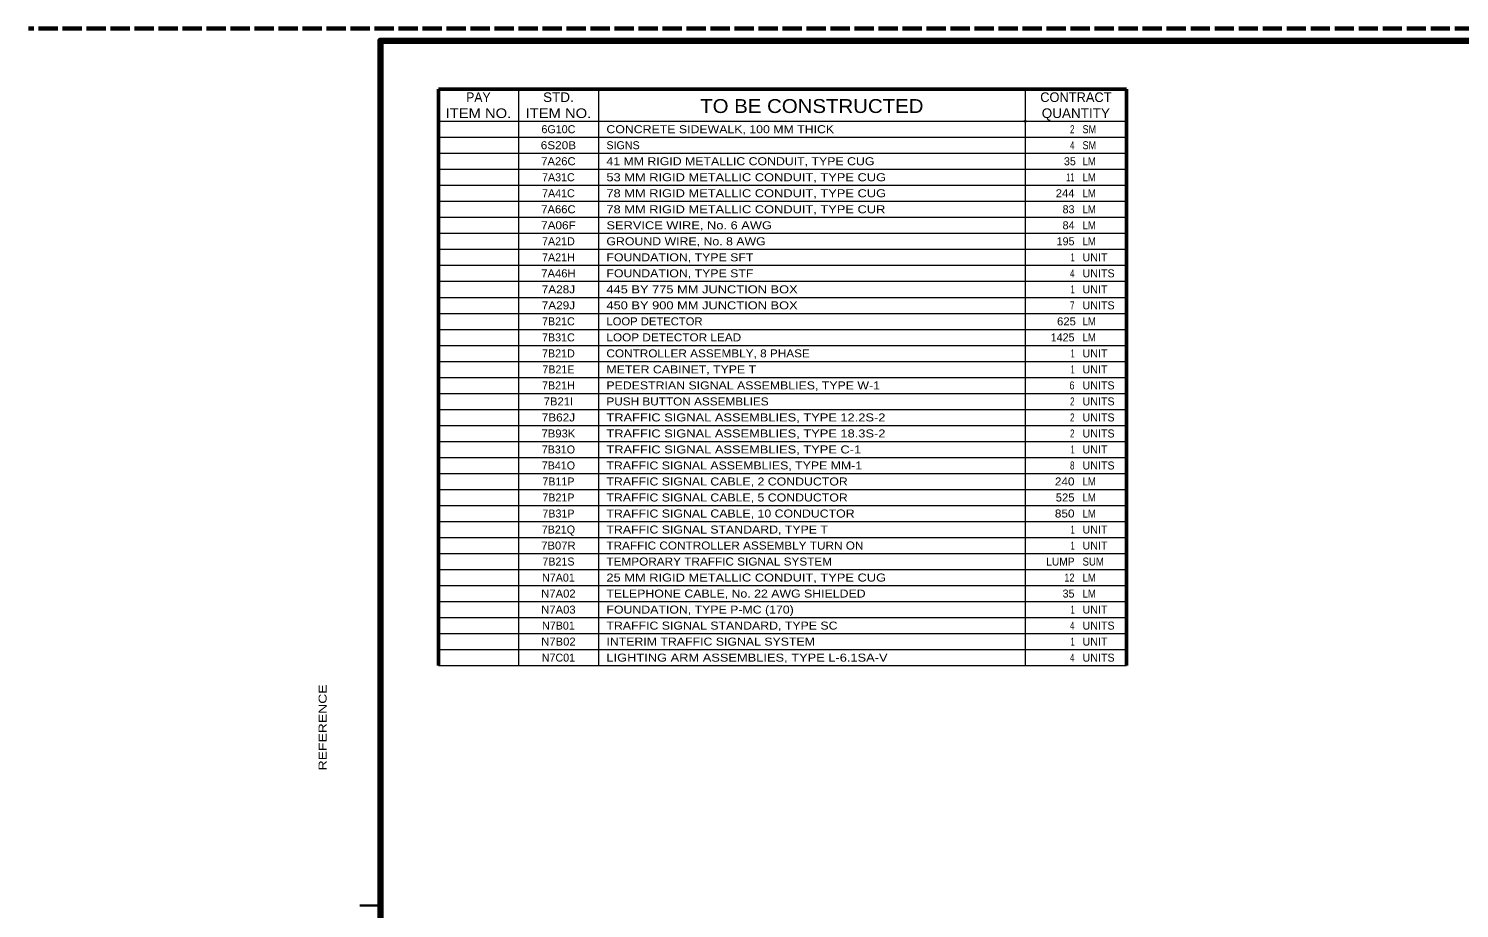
# Model space of a CAD drawing. Extents: x 168203 to 169864, y 223196 to 223870.
# Drawn here: x 169095.8 to 169229.9, y 223449.3 to 223531.7 of the extents above; entities that cross this region are included whole.
import ezdxf
from ezdxf.enums import TextEntityAlignment as Align

# ---------------------------------------------------------------- set-up
doc = ezdxf.new("R2010")
doc.units = 0
doc.header["$LTSCALE"] = 0.3
doc.header["$PDMODE"] = 32
doc.header["$PDSIZE"] = 0.15
doc.linetypes.add('LONG_DASHED', pattern=[7.5, 6, -1.5])
doc.layers.add('1', color=7, linetype='Continuous', lineweight=13)
doc.layers.add('10', color=7, linetype='Continuous', lineweight=13)

msp = doc.modelspace()

# ---------------------------------------------------------------- linework, layer by layer
at = {"layer": '1', "linetype": 'LONG_DASHED', "lineweight": 60}
msp.add_line((169364.0333, 223531.7489), (169095.8093, 223531.7489), dxfattribs=at)
at = {"layer": '1', "lineweight": 35}
msp.add_line((169126.8633, 223449.6089), (169128.7833, 223449.6089), dxfattribs=at)
at = {"layer": '1', "lineweight": 158}
msp.add_lwpolyline([(169361.2833, 223368.6089), (169361.2833, 223530.6089), (169128.7833, 223530.6089), (169128.7833, 223368.6089)], close=True, dxfattribs=at)
at = {"layer": '10', "lineweight": 53}
for p, q in [((169134.22, 223526.0771), (169198.72, 223526.0771)), ((169134.22, 223523.0771), (169134.22, 223526.0771)), ((169198.72, 223526.0771), (169198.72, 223523.0771)), ((169134.22, 223521.5771), (169134.22, 223523.0771)), ((169198.72, 223523.0771), (169198.72, 223521.5771)), ((169134.22, 223520.0771), (169134.22, 223521.5771)), ((169198.72, 223521.5771), (169198.72, 223520.0771)), ((169134.22, 223518.5771), (169134.22, 223520.0771)), ((169198.72, 223520.0771), (169198.72, 223518.5771)), ((169134.22, 223517.0771), (169134.22, 223518.5771)), ((169198.72, 223518.5771), (169198.72, 223517.0771)), ((169134.22, 223515.5771), (169134.22, 223517.0771)), ((169198.72, 223517.0771), (169198.72, 223515.5771)), ((169134.22, 223514.0771), (169134.22, 223515.5771)), ((169198.72, 223515.5771), (169198.72, 223514.0771)), ((169134.22, 223512.5771), (169134.22, 223514.0771)), ((169198.72, 223514.0771), (169198.72, 223512.5771)), ((169134.22, 223511.0771), (169134.22, 223512.5771)), ((169198.72, 223512.5771), (169198.72, 223511.0771)), ((169134.22, 223509.5771), (169134.22, 223511.0771)), ((169198.72, 223511.0771), (169198.72, 223509.5771)), ((169134.22, 223508.0771), (169134.22, 223509.5771)), ((169198.72, 223509.5771), (169198.72, 223508.0771)), ((169134.22, 223506.5771), (169134.22, 223508.0771)), ((169198.72, 223508.0771), (169198.72, 223506.5771)), ((169134.22, 223505.0771), (169134.22, 223506.5771)), ((169198.72, 223506.5771), (169198.72, 223505.0771)), ((169134.22, 223503.5771), (169134.22, 223505.0771)), ((169198.72, 223505.0771), (169198.72, 223503.5771)), ((169134.22, 223502.0771), (169134.22, 223503.5771)), ((169198.72, 223503.5771), (169198.72, 223502.0771)), ((169134.22, 223500.5771), (169134.22, 223502.0771)), ((169198.72, 223502.0771), (169198.72, 223500.5771)), ((169134.22, 223499.0771), (169134.22, 223500.5771)), ((169198.72, 223500.5771), (169198.72, 223499.0771)), ((169134.22, 223497.5771), (169134.22, 223499.0771)), ((169198.72, 223499.0771), (169198.72, 223497.5771)), ((169134.22, 223496.0771), (169134.22, 223497.5771)), ((169198.72, 223497.5771), (169198.72, 223496.0771)), ((169134.22, 223494.5771), (169134.22, 223496.0771)), ((169198.72, 223496.0771), (169198.72, 223494.5771)), ((169134.22, 223493.0771), (169134.22, 223494.5771)), ((169198.72, 223494.5771), (169198.72, 223493.0771)), ((169134.22, 223491.5771), (169134.22, 223493.0771)), ((169198.72, 223493.0771), (169198.72, 223491.5771)), ((169134.22, 223490.0771), (169134.22, 223491.5771)), ((169198.72, 223491.5771), (169198.72, 223490.0771)), ((169134.22, 223488.5771), (169134.22, 223490.0771)), ((169198.72, 223490.0771), (169198.72, 223488.5771)), ((169134.22, 223487.0771), (169134.22, 223488.5771)), ((169198.72, 223488.5771), (169198.72, 223487.0771)), ((169134.22, 223485.5771), (169134.22, 223487.0771)), ((169198.72, 223487.0771), (169198.72, 223485.5771)), ((169134.22, 223484.0771), (169134.22, 223485.5771)), ((169198.72, 223485.5771), (169198.72, 223484.0771)), ((169134.22, 223482.5771), (169134.22, 223484.0771)), ((169198.72, 223484.0771), (169198.72, 223482.5771)), ((169134.22, 223481.0771), (169134.22, 223482.5771)), ((169198.72, 223482.5771), (169198.72, 223481.0771)), ((169134.22, 223479.5771), (169134.22, 223481.0771)), ((169198.72, 223481.0771), (169198.72, 223479.5771)), ((169134.22, 223478.0771), (169134.22, 223479.5771)), ((169198.72, 223479.5771), (169198.72, 223478.0771)), ((169134.22, 223476.5771), (169134.22, 223478.0771)), ((169198.72, 223478.0771), (169198.72, 223476.5771)), ((169134.22, 223475.0771), (169134.22, 223476.5771)), ((169198.72, 223476.5771), (169198.72, 223475.0771)), ((169134.22, 223473.5771), (169134.22, 223475.0771)), ((169198.72, 223475.0771), (169198.72, 223473.5771)), ((169134.22, 223472.0771), (169134.22, 223473.5771)), ((169198.72, 223473.5771), (169198.72, 223472.0771))]:
    msp.add_line(p, q, dxfattribs=at)
at = {"layer": '10'}
for p, q in [((169141.72, 223526.0771), (169141.72, 223523.0771)), ((169149.22, 223526.0771), (169149.22, 223523.0771)), ((169189.22, 223526.0771), (169189.22, 223523.0771)), ((169134.22, 223523.0771), (169198.72, 223523.0771)), ((169141.72, 223523.0771), (169141.72, 223521.5771)), ((169149.22, 223523.0771), (169149.22, 223521.5771)), ((169189.22, 223523.0771), (169189.22, 223521.5771)), ((169134.22, 223521.5771), (169198.72, 223521.5771)), ((169141.72, 223521.5771), (169141.72, 223520.0771)), ((169149.22, 223521.5771), (169149.22, 223520.0771)), ((169189.22, 223521.5771), (169189.22, 223520.0771)), ((169134.22, 223520.0771), (169198.72, 223520.0771)), ((169141.72, 223520.0771), (169141.72, 223518.5771)), ((169149.22, 223520.0771), (169149.22, 223518.5771)), ((169189.22, 223520.0771), (169189.22, 223518.5771)), ((169134.22, 223518.5771), (169198.72, 223518.5771)), ((169141.72, 223518.5771), (169141.72, 223517.0771)), ((169149.22, 223518.5771), (169149.22, 223517.0771)), ((169189.22, 223518.5771), (169189.22, 223517.0771)), ((169134.22, 223517.0771), (169198.72, 223517.0771)), ((169141.72, 223517.0771), (169141.72, 223515.5771)), ((169149.22, 223517.0771), (169149.22, 223515.5771)), ((169189.22, 223517.0771), (169189.22, 223515.5771)), ((169134.22, 223515.5771), (169198.72, 223515.5771)), ((169141.72, 223515.5771), (169141.72, 223514.0771)), ((169149.22, 223515.5771), (169149.22, 223514.0771)), ((169189.22, 223515.5771), (169189.22, 223514.0771)), ((169134.22, 223514.0771), (169198.72, 223514.0771)), ((169141.72, 223514.0771), (169141.72, 223512.5771)), ((169149.22, 223514.0771), (169149.22, 223512.5771)), ((169189.22, 223514.0771), (169189.22, 223512.5771)), ((169134.22, 223512.5771), (169198.72, 223512.5771)), ((169141.72, 223512.5771), (169141.72, 223511.0771)), ((169149.22, 223512.5771), (169149.22, 223511.0771)), ((169189.22, 223512.5771), (169189.22, 223511.0771)), ((169134.22, 223511.0771), (169198.72, 223511.0771)), ((169141.72, 223511.0771), (169141.72, 223509.5771)), ((169149.22, 223511.0771), (169149.22, 223509.5771)), ((169189.22, 223511.0771), (169189.22, 223509.5771)), ((169134.22, 223509.5771), (169198.72, 223509.5771)), ((169141.72, 223509.5771), (169141.72, 223508.0771)), ((169149.22, 223509.5771), (169149.22, 223508.0771)), ((169189.22, 223509.5771), (169189.22, 223508.0771)), ((169134.22, 223508.0771), (169198.72, 223508.0771)), ((169141.72, 223508.0771), (169141.72, 223506.5771)), ((169149.22, 223508.0771), (169149.22, 223506.5771)), ((169189.22, 223508.0771), (169189.22, 223506.5771)), ((169134.22, 223506.5771), (169198.72, 223506.5771)), ((169141.72, 223506.5771), (169141.72, 223505.0771)), ((169149.22, 223506.5771), (169149.22, 223505.0771)), ((169189.22, 223506.5771), (169189.22, 223505.0771)), ((169134.22, 223505.0771), (169198.72, 223505.0771)), ((169141.72, 223505.0771), (169141.72, 223503.5771)), ((169149.22, 223505.0771), (169149.22, 223503.5771)), ((169189.22, 223505.0771), (169189.22, 223503.5771)), ((169134.22, 223503.5771), (169198.72, 223503.5771)), ((169141.72, 223503.5771), (169141.72, 223502.0771)), ((169149.22, 223503.5771), (169149.22, 223502.0771)), ((169189.22, 223503.5771), (169189.22, 223502.0771)), ((169134.22, 223502.0771), (169198.72, 223502.0771)), ((169141.72, 223502.0771), (169141.72, 223500.5771)), ((169149.22, 223502.0771), (169149.22, 223500.5771)), ((169189.22, 223502.0771), (169189.22, 223500.5771)), ((169134.22, 223500.5771), (169198.72, 223500.5771)), ((169141.72, 223500.5771), (169141.72, 223499.0771)), ((169149.22, 223500.5771), (169149.22, 223499.0771)), ((169189.22, 223500.5771), (169189.22, 223499.0771)), ((169134.22, 223499.0771), (169198.72, 223499.0771)), ((169141.72, 223499.0771), (169141.72, 223497.5771)), ((169149.22, 223499.0771), (169149.22, 223497.5771)), ((169189.22, 223499.0771), (169189.22, 223497.5771)), ((169134.22, 223497.5771), (169198.72, 223497.5771)), ((169141.72, 223497.5771), (169141.72, 223496.0771)), ((169149.22, 223497.5771), (169149.22, 223496.0771)), ((169189.22, 223497.5771), (169189.22, 223496.0771)), ((169134.22, 223496.0771), (169198.72, 223496.0771)), ((169141.72, 223496.0771), (169141.72, 223494.5771)), ((169149.22, 223496.0771), (169149.22, 223494.5771)), ((169189.22, 223496.0771), (169189.22, 223494.5771)), ((169134.22, 223494.5771), (169198.72, 223494.5771)), ((169141.72, 223494.5771), (169141.72, 223493.0771)), ((169149.22, 223494.5771), (169149.22, 223493.0771)), ((169189.22, 223494.5771), (169189.22, 223493.0771)), ((169134.22, 223493.0771), (169198.72, 223493.0771)), ((169141.72, 223493.0771), (169141.72, 223491.5771)), ((169149.22, 223493.0771), (169149.22, 223491.5771)), ((169189.22, 223493.0771), (169189.22, 223491.5771)), ((169134.22, 223491.5771), (169198.72, 223491.5771)), ((169141.72, 223491.5771), (169141.72, 223490.0771)), ((169149.22, 223491.5771), (169149.22, 223490.0771)), ((169189.22, 223491.5771), (169189.22, 223490.0771)), ((169134.22, 223490.0771), (169198.72, 223490.0771)), ((169141.72, 223490.0771), (169141.72, 223488.5771)), ((169149.22, 223490.0771), (169149.22, 223488.5771)), ((169189.22, 223490.0771), (169189.22, 223488.5771)), ((169134.22, 223488.5771), (169198.72, 223488.5771)), ((169141.72, 223488.5771), (169141.72, 223487.0771)), ((169149.22, 223488.5771), (169149.22, 223487.0771)), ((169189.22, 223488.5771), (169189.22, 223487.0771)), ((169134.22, 223487.0771), (169198.72, 223487.0771)), ((169141.72, 223487.0771), (169141.72, 223485.5771)), ((169149.22, 223487.0771), (169149.22, 223485.5771)), ((169189.22, 223487.0771), (169189.22, 223485.5771)), ((169134.22, 223485.5771), (169198.72, 223485.5771)), ((169141.72, 223485.5771), (169141.72, 223484.0771)), ((169149.22, 223485.5771), (169149.22, 223484.0771)), ((169189.22, 223485.5771), (169189.22, 223484.0771)), ((169134.22, 223484.0771), (169198.72, 223484.0771)), ((169141.72, 223484.0771), (169141.72, 223482.5771)), ((169149.22, 223484.0771), (169149.22, 223482.5771)), ((169189.22, 223484.0771), (169189.22, 223482.5771)), ((169134.22, 223482.5771), (169198.72, 223482.5771)), ((169141.72, 223482.5771), (169141.72, 223481.0771)), ((169149.22, 223482.5771), (169149.22, 223481.0771)), ((169189.22, 223482.5771), (169189.22, 223481.0771)), ((169134.22, 223481.0771), (169198.72, 223481.0771)), ((169141.72, 223481.0771), (169141.72, 223479.5771)), ((169149.22, 223481.0771), (169149.22, 223479.5771)), ((169189.22, 223481.0771), (169189.22, 223479.5771)), ((169134.22, 223479.5771), (169198.72, 223479.5771)), ((169141.72, 223479.5771), (169141.72, 223478.0771)), ((169149.22, 223479.5771), (169149.22, 223478.0771)), ((169189.22, 223479.5771), (169189.22, 223478.0771)), ((169134.22, 223478.0771), (169198.72, 223478.0771)), ((169141.72, 223478.0771), (169141.72, 223476.5771)), ((169149.22, 223478.0771), (169149.22, 223476.5771)), ((169189.22, 223478.0771), (169189.22, 223476.5771)), ((169134.22, 223476.5771), (169198.72, 223476.5771)), ((169141.72, 223476.5771), (169141.72, 223475.0771)), ((169149.22, 223476.5771), (169149.22, 223475.0771)), ((169189.22, 223476.5771), (169189.22, 223475.0771)), ((169134.22, 223475.0771), (169198.72, 223475.0771)), ((169141.72, 223475.0771), (169141.72, 223473.5771)), ((169149.22, 223475.0771), (169149.22, 223473.5771)), ((169189.22, 223475.0771), (169189.22, 223473.5771)), ((169134.22, 223473.5771), (169198.72, 223473.5771)), ((169141.72, 223473.5771), (169141.72, 223472.0771)), ((169149.22, 223473.5771), (169149.22, 223472.0771)), ((169189.22, 223473.5771), (169189.22, 223472.0771)), ((169134.22, 223472.0771), (169198.72, 223472.0771))]:
    msp.add_line(p, q, dxfattribs=at)
for p in [(169189.22, 223526.0771), (169189.22, 223523.0771)]:
    msp.add_point(p, dxfattribs=at)

# ---------------------------------------------------------------- texts
at = {"layer": '1', "width": 1.3}
msp.add_text('REFERENCE                                                              ', height=0.75, rotation=90, dxfattribs=at).set_placement((169123.7433, 223462.2689))
at = {"layer": '10'}
for s, height, width, p in [('PAY', 0.9, 0.95, (169137.97, 223524.8771)), ('STD.', 0.9, 1.05, (169145.4701, 223524.8771)), ('TO BE CONSTRUCTED', 1.3, 1.1, (169169.2252, 223523.8472)), ('ITEM NO.', 0.9, 1.15, (169137.97, 223523.3771)), ('ITEM NO.', 0.9, 1.15, (169145.47, 223523.3771)), ('QUANTITY', 0.9, 1.05, (169193.9701, 223523.3771)), ('6S20B', 0.75, 1.1, (169145.4699, 223520.4521)), ('7A26C', 0.75, 1.05, (169145.4698, 223518.9521)), ('7A66C', 0.75, 1.05, (169145.4699, 223514.4521)), ('7A06F', 0.75, 1.1, (169145.4698, 223512.9521)), ('7A46H', 0.75, 1.05, (169145.4699, 223508.4521)), ('7A28J', 0.75, 1.1, (169145.4698, 223506.9521)), ('7A29J', 0.75, 1.1, (169145.4698, 223505.4521)), ('7B21I', 0.75, 1.05, (169145.4699, 223496.4521)), ('7B62J', 0.75, 1.1, (169145.4699, 223494.9521)), ('7B93K', 0.75, 1.05, (169145.4698, 223493.4521)), ('7B07R', 0.75, 1.05, (169145.4698, 223482.9521)), ('N7A02', 0.75, 1.05, (169145.4699, 223478.4521)), ('N7A03', 0.75, 1.05, (169145.4699, 223476.9521)), ('N7B02', 0.75, 1.05, (169145.4699, 223473.9521))]:
    msp.add_text(s, height=height, dxfattribs=dict(at, width=width)).set_placement(p, align=Align.CENTER)
for s, height, p in [('CONTRACT', 0.9, (169193.9735, 223524.8771)), ('6G10C', 0.75, (169145.4699, 223521.9521)), ('7A31C', 0.75, (169145.4698, 223517.4521)), ('7A41C', 0.75, (169145.4698, 223515.9521)), ('7A21D', 0.75, (169145.4698, 223511.4521)), ('7A21H', 0.75, (169145.4699, 223509.9521)), ('7B21C', 0.75, (169145.4698, 223503.9521)), ('7B31C', 0.75, (169145.4698, 223502.4521)), ('7B21D', 0.75, (169145.4698, 223500.9521)), ('7B21E', 0.75, (169145.4699, 223499.4521)), ('7B21H', 0.75, (169145.4699, 223497.9521)), ('7B31O', 0.75, (169145.4698, 223491.9521)), ('7B41O', 0.75, (169145.4698, 223490.4521)), ('7B11P', 0.75, (169145.4699, 223488.9521)), ('7B21P', 0.75, (169145.4698, 223487.4521)), ('7B31P', 0.75, (169145.4698, 223485.9521)), ('7B21Q', 0.75, (169145.4698, 223484.4521)), ('7B21S', 0.75, (169145.4699, 223481.4521)), ('N7A01', 0.75, (169145.4699, 223479.9521)), ('N7B01', 0.75, (169145.4698, 223475.4521)), ('N7C01', 0.75, (169145.4698, 223472.4521))]:
    msp.add_text(s, height=height, dxfattribs=at).set_placement(p, align=Align.CENTER)
for s, width, p in [('CONCRETE SIDEWALK, 100 MM THICK', 1.15, (169149.97, 223521.9521)), ('SM', 0.85, (169194.595, 223521.9521)), ('SM', 0.85, (169194.595, 223520.4521)), ('41 MM RIGID METALLIC CONDUIT, TYPE CUG', 1.15, (169149.97, 223518.9521)), ('LM', 0.9, (169194.595, 223518.9521)), ('53 MM RIGID METALLIC CONDUIT, TYPE CUG', 1.2, (169149.97, 223517.4521)), ('LM', 0.9, (169194.595, 223517.4521)), ('78 MM RIGID METALLIC CONDUIT, TYPE CUG', 1.2, (169149.97, 223515.9521)), ('LM', 0.9, (169194.595, 223515.9521)), ('78 MM RIGID METALLIC CONDUIT, TYPE CUR', 1.2, (169149.97, 223514.4521)), ('LM', 0.9, (169194.595, 223514.4521)), ('SERVICE WIRE, No. 6 AWG', 1.2, (169149.97, 223512.9521)), ('LM', 0.9, (169194.595, 223512.9521)), ('GROUND WIRE, No. 8 AWG', 1.15, (169149.97, 223511.4521)), ('LM', 0.9, (169194.595, 223511.4521)), ('FOUNDATION, TYPE SFT', 1.15, (169149.97, 223509.9521)), ('FOUNDATION, TYPE STF', 1.15, (169149.97, 223508.4521)), ('445 BY 775 MM JUNCTION BOX', 1.2, (169149.97, 223506.9521)), ('450 BY 900 MM JUNCTION BOX', 1.2, (169149.97, 223505.4521)), ('LOOP DETECTOR', 1.05, (169149.97, 223503.9521)), ('LM', 0.9, (169194.595, 223503.9521)), ('LOOP DETECTOR LEAD', 1.1, (169149.97, 223502.4521)), ('LM', 0.9, (169194.595, 223502.4521)), ('CONTROLLER ASSEMBLY, 8 PHASE', 1.1, (169149.97, 223500.9521)), ('METER CABINET, TYPE T', 1.15, (169149.97, 223499.4521)), ('PEDESTRIAN SIGNAL ASSEMBLIES, TYPE W-1', 1.15, (169149.97, 223497.9521)), ('PUSH BUTTON ASSEMBLIES', 1.1, (169149.97, 223496.4521)), ('TRAFFIC SIGNAL ASSEMBLIES, TYPE 12.2S-2', 1.2, (169149.97, 223494.9521)), ('TRAFFIC SIGNAL ASSEMBLIES, TYPE 18.3S-2', 1.2, (169149.97, 223493.4521)), ('TRAFFIC SIGNAL ASSEMBLIES, TYPE C-1', 1.2, (169149.97, 223491.9521)), ('TRAFFIC SIGNAL ASSEMBLIES, TYPE MM-1', 1.15, (169149.97, 223490.4521)), ('TRAFFIC SIGNAL CABLE, 2 CONDUCTOR', 1.15, (169149.97, 223488.9521)), ('LM', 0.9, (169194.595, 223488.9521)), ('TRAFFIC SIGNAL CABLE, 5 CONDUCTOR', 1.15, (169149.97, 223487.4521)), ('LM', 0.9, (169194.595, 223487.4521)), ('TRAFFIC SIGNAL CABLE, 10 CONDUCTOR', 1.15, (169149.97, 223485.9521)), ('LM', 0.9, (169194.595, 223485.9521)), ('TRAFFIC SIGNAL STANDARD, TYPE T', 1.15, (169149.97, 223484.4521)), ('TRAFFIC CONTROLLER ASSEMBLY TURN ON', 1.1, (169149.97, 223482.9521)), ('TEMPORARY TRAFFIC SIGNAL SYSTEM', 1.1, (169149.97, 223481.4521)), ('SUM', 0.9, (169194.595, 223481.4521)), ('25 MM RIGID METALLIC CONDUIT, TYPE CUG', 1.2, (169149.97, 223479.9521)), ('LM', 0.9, (169194.595, 223479.9521)), ('TELEPHONE CABLE, No. 22 AWG SHIELDED', 1.15, (169149.97, 223478.4521)), ('LM', 0.9, (169194.595, 223478.4521)), ('FOUNDATION, TYPE P-MC (170)', 1.15, (169149.97, 223476.9521)), ('TRAFFIC SIGNAL STANDARD, TYPE SC', 1.15, (169149.97, 223475.4521)), ('INTERIM TRAFFIC SIGNAL SYSTEM', 1.15, (169149.97, 223473.9521)), ('LIGHTING ARM ASSEMBLIES, TYPE L-6.1SA-V', 1.2, (169149.97, 223472.4521))]:
    msp.add_text(s, height=0.75, dxfattribs=dict(at, width=width)).set_placement(p)
for s, width, p in [('2', 0.75, (169193.845, 223521.9521)), ('4', 0.75, (169193.845, 223520.4521)), ('11', 0.7, (169193.845, 223517.4521)), ('244', 1.05, (169193.845, 223515.9521)), ('1', 0.5, (169193.845, 223509.9521)), ('4', 0.75, (169193.845, 223508.4521)), ('1', 0.5, (169193.845, 223506.9521)), ('7', 0.75, (169193.845, 223505.4521)), ('625', 1.05, (169193.97, 223503.9521)), ('1', 0.5, (169193.845, 223500.9521)), ('1', 0.5, (169193.845, 223499.4521)), ('6', 0.85, (169193.845, 223497.9521)), ('2', 0.75, (169193.845, 223496.4521)), ('2', 0.75, (169193.845, 223494.9521)), ('2', 0.75, (169193.845, 223493.4521)), ('1', 0.5, (169193.845, 223491.9521)), ('8', 0.75, (169193.845, 223490.4521)), ('240', 1.1, (169193.845, 223488.9521)), ('525', 1.05, (169193.845, 223487.4521)), ('850', 1.1, (169193.845, 223485.9521)), ('1', 0.5, (169193.845, 223484.4521)), ('1', 0.5, (169193.845, 223482.9521)), ('LUMP', 0.95, (169193.845, 223481.4521)), ('12', 0.85, (169193.845, 223479.9521)), ('1', 0.5, (169193.845, 223476.9521)), ('4', 0.75, (169193.845, 223475.4521)), ('1', 0.5, (169193.845, 223473.9521)), ('4', 0.75, (169193.845, 223472.4521))]:
    msp.add_text(s, height=0.75, dxfattribs=dict(at, width=width)).set_placement(p, align=Align.RIGHT)
for s, p in [('SIGNS', (169149.97, 223520.4521)), ('UNIT', (169194.595, 223509.9521)), ('UNITS', (169194.595, 223508.4521)), ('UNIT', (169194.595, 223506.9521)), ('UNITS', (169194.595, 223505.4521)), ('UNIT', (169194.595, 223500.9521)), ('UNIT', (169194.595, 223499.4521)), ('UNITS', (169194.595, 223497.9521)), ('UNITS', (169194.595, 223496.4521)), ('UNITS', (169194.595, 223494.9521)), ('UNITS', (169194.595, 223493.4521)), ('UNIT', (169194.595, 223491.9521)), ('UNITS', (169194.595, 223490.4521)), ('UNIT', (169194.595, 223484.4521)), ('UNIT', (169194.595, 223482.9521)), ('UNIT', (169194.595, 223476.9521)), ('UNITS', (169194.595, 223475.4521)), ('UNIT', (169194.595, 223473.9521)), ('UNITS', (169194.595, 223472.4521))]:
    msp.add_text(s, height=0.75, dxfattribs=at).set_placement(p)
for s, p in [('35', (169193.97, 223518.9521)), ('83', (169193.845, 223514.4521)), ('84', (169193.845, 223512.9521)), ('195', (169193.845, 223511.4521)), ('1425', (169193.845, 223502.4521)), ('35', (169193.845, 223478.4521))]:
    msp.add_text(s, height=0.75, dxfattribs=at).set_placement(p, align=Align.RIGHT)

doc.saveas('drawing.dxf')
